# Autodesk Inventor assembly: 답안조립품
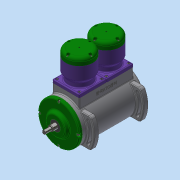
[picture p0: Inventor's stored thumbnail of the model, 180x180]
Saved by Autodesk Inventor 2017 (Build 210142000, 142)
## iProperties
Part Number: 답안조립품
Material: 일반
Document SubType Name: Assembly
Designer: Administrator
Author: Administrator
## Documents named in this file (16)
- C:\Users\Administrator\Desktop\620106V1006\답안조립품.iam
- C:\Users\Administrator\Desktop\620106V1006\본체.ipt
- C:\Users\Administrator\Desktop\620106V1006\크랭크축.ipt
- C:\Users\Administrator\Desktop\620106V1006\베어링 6303.ipt
- C:\Users\Administrator\Desktop\620106V1006\앞커버.ipt
- C:\Users\Administrator\Desktop\620106V1006\볼트 M4 x 12.ipt
- C:\Users\Administrator\Desktop\620106V1006\오일 실 17 x 32 x 8.ipt
- C:\Users\Administrator\Desktop\620106V1006\실린더.ipt
- C:\Users\Administrator\Desktop\620106V1006\실린더헤드.ipt
- C:\Users\Administrator\Desktop\620106V1006\볼트 M5 x 20.ipt
- C:\Users\Administrator\Desktop\620106V1006\피스톤.ipt
- C:\Users\Administrator\Desktop\620106V1006\피스톤핀.ipt
- C:\Users\Administrator\Desktop\620106V1006\커넥팅로드.ipt
- C:\Users\Administrator\Desktop\620106V1006\커넥팅로드 엔드.ipt
- C:\Users\Administrator\Desktop\620106V1006\육각 머리 볼트 M4 x 16.ipt
- C:\Users\Administrator\Desktop\620106V1006\너트 M4.ipt
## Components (4 placed, 2 different names)
1. 피스톤:1
2. 피스톤핀:1
3. 피스톤:2
4. 피스톤핀:2
